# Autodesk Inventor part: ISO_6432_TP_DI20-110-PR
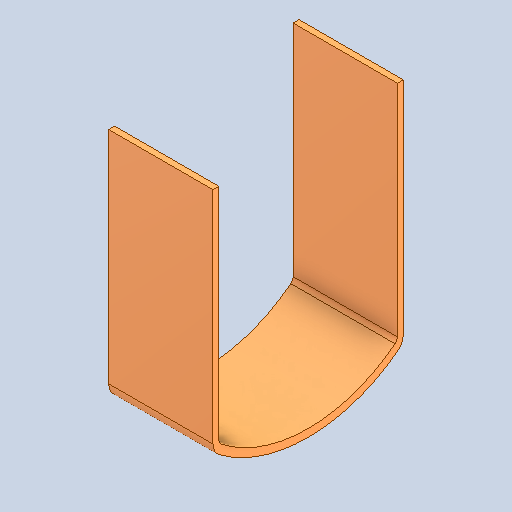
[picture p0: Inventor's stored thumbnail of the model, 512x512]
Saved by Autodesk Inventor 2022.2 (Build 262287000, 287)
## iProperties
Created: 2024-10
Part Number: ISO_6432_TP_DI20-110-PR
Material: Generico
Document SubType Name: Modeling
Designer: 18907419
Density: 1 g/cm^3
Appearance: Default
Author: 18907419
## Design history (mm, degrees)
feature "Solid1"
node "Solido1"
